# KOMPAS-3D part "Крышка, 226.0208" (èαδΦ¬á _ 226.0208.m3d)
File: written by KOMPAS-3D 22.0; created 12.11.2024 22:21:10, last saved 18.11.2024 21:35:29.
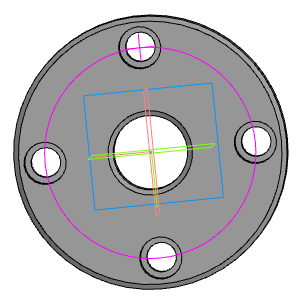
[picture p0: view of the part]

Document properties: Автор: aleksander.larionov.10@gmail.com; Полное имя файла: C:\Мои папки\Работа\Крышки, фланцы\226.0208\Крышка _ 226.0208.m3d

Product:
- Part/product: Крышка  | designation 226.0208
    Материал: Сталь 45 ГОСТ 1050-2013 (density 7810 kg/m3)
    Масса: 1.120135

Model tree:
1. Эскиз:1
2. Элемент выдавливания:1
     Расстояние 1 = 18
3. Эскиз:2  (with: Элемент выдавливания:1)
4. Отверстие:1  (with: Элемент выдавливания:1)
     Глубина выреза = 18; Диаметр отверстия = 12; Угол конуса дна = 118; Расстояние 1 = 42.5; Диаметр цековки = 17; Глубина цековки = 11
5. Массив по концентрической сетке:1  (with: Отверстие:1)  (4 pattern instances)
     Шаг 2 = 360
6. Фаска:1  (with: Элемент выдавливания:1)  (labels: Сталь 45 ГОСТ 1050-2013)
     Угол = 45; Длина 1 = 2; Длина 2 = 2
